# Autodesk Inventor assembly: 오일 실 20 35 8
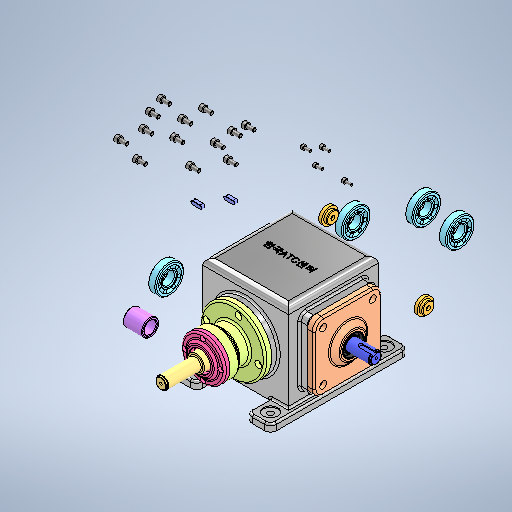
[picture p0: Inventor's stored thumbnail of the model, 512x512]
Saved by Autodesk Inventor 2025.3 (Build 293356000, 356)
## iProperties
Created: 2026-01
Part Number: 오일 실 20 35 8
Material: 고무
Description: 오일-실
Document SubType Name: Modeling
Designer: PC01-12
Density: 0.93 g/cm^3
Appearance: 기본값
Author: jhkim
Sending System: Autodesk Inventor 2026
Preprocessor: ST-DEVELOPER v20.1
Part Number: 테이퍼 롤러 베어링 30204K
Material: 강철, 연강
Description: 테이퍼 롤러 베어링
Density: 7.85 g/cm^3
Part Number: 엔드캡
Part Number: 구동축
Material: 강철, 탄소
Part Number: 6각 구멍붙이 볼트 M6x12
Description: 6각머리 태핑 나사
Part Number: 측면 커버
Material: 알루미늄 6061
Density: 2.7 g/cm^3
Part Number: 베어링 하우징
Part Number: 하우징 커버
Part Number: 칼라
Part Number: 종동축
Part Number: 평행 키 6x6x18
Description: 키 및 해당 키홈
Part Number: 6각 구멍붙이 볼트 M4x10
Part Number: 답안조립품
Document SubType Name: Assembly
Author: PC01-12
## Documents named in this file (26)
- **C:\Users\PC01-12\Desktop\760103V1014\답안조립품.iam*LocalDocs*xAaaaaodaAaaaaaaaAaaaq2g10a*오일 실 20 35 8.ipt
- **C:\Users\PC01-12\Desktop\760103V1014\답안조립품.iam*LocalDocs*xAaaaa4daAaaaaaaaAaaaq2vd1f*테이퍼 롤러 베어링 30204K.ipt
- **C:\Users\PC01-12\Desktop\760103V1014\답안조립품.iam*LocalDocs*xAaaaa4aaAaaaaaaaAaaaqcwaYd*엔드캡.ipt
- **C:\Users\PC01-12\Desktop\760103V1014\답안조립품.iam*LocalDocs*xAaaaa1aaAaaaaaaaAaaaqsygNb*구동축.ipt
- **C:\Users\PC01-12\Desktop\760103V1014\답안조립품.iam*LocalDocs*xAaaaafcaAaaaaaaaAaaaqlk1Sg*6각 구멍붙이 볼트 M6x12.ipt
- **C:\Users\PC01-12\Desktop\760103V1014\답안조립품.iam*LocalDocs*xAaaaafaaAaaaaaaaAaaaa5neWb*측면 커버.ipt
- **C:\Users\PC01-12\Desktop\760103V1014\답안조립품.iam*LocalDocs*xAaaaafdaAaaaaaaaAaaaazimQh*베어링 하우징.ipt
- **C:\Users\PC01-12\Desktop\760103V1014\답안조립품.iam*LocalDocs*xAaaaqfaaAaaaaaaaAaaaqaciDc*하우징 커버.ipt
- **C:\Users\PC01-12\Desktop\760103V1014\답안조립품.iam*LocalDocs*xAaaaaybaAaaaaaaaAaaaqojzGd*칼라.ipt
- **C:\Users\PC01-12\Desktop\760103V1014\답안조립품.iam*LocalDocs*xAaaaq3baAaaaaaaaAaaaquoqIh*종동축.ipt
- **C:\Users\PC01-12\Desktop\760103V1014\답안조립품.iam*LocalDocs*xAaaaqtaaAaaaaaaaAaaaaspwLh*평행 키 6x6x18.ipt
- **C:\Users\PC01-12\Desktop\760103V1014\답안조립품.iam*LocalDocs*xAaaaqoaaAaaaaaaaAaaaabrq4f*6각 구멍붙이 볼트 M4x10.ipt
- C:\Users\PC01-12\Desktop\760103V1014\답안조립품.iam
- C:\Users\PC01-12\Documents\Inventor\760103V1014\본체.ipt
- C:\Users\PC01-12\Desktop\760103V1014\6각 구멍붙이 볼트 M4x10.stp
- C:\Users\PC01-12\Desktop\760103V1014\6각 구멍붙이 볼트 M6x12.stp
- C:\Users\PC01-12\Desktop\760103V1014\종동축.stp
- C:\Users\PC01-12\Desktop\760103V1014\테이퍼 롤러 베어링 30204K.stp
- C:\Users\PC01-12\Desktop\760103V1014\측면 커버.stp
- C:\Users\PC01-12\Desktop\760103V1014\평행 키 6x6x18.stp
- C:\Users\PC01-12\Desktop\760103V1014\하우징 커버.stp
- C:\Users\PC01-12\Desktop\760103V1014\엔드캡.stp
- C:\Users\PC01-12\Desktop\760103V1014\오일 실 20 35 8.stp
- C:\Users\PC01-12\Desktop\760103V1014\칼라.stp
- C:\Users\PC01-12\Desktop\760103V1014\구동축.stp
- C:\Users\PC01-12\Desktop\760103V1014\베어링 하우징.stp
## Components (19 placed, 4 different names)
1. 6각 구멍붙이 볼트 M4x10:1
2. 6각 구멍붙이 볼트 M4x10:2
3. 6각 구멍붙이 볼트 M4x10:3
4. 6각 구멍붙이 볼트 M4x10:4
5. 6각 구멍붙이 볼트 M6x12:1
6. 6각 구멍붙이 볼트 M6x12:2
7. 6각 구멍붙이 볼트 M6x12:3
8. 6각 구멍붙이 볼트 M6x12:4
9. 6각 구멍붙이 볼트 M6x12:5
10. 6각 구멍붙이 볼트 M6x12:6
11. 6각 구멍붙이 볼트 M6x12:7
12. 6각 구멍붙이 볼트 M6x12:8
13. 6각 구멍붙이 볼트 M6x12:9
14. 6각 구멍붙이 볼트 M6x12:10
15. 6각 구멍붙이 볼트 M6x12:11
16. 6각 구멍붙이 볼트 M6x12:12
17. 6각 구멍붙이 볼트 M6x12:13
18. 하우징 커버:1
19. 구동축:1
